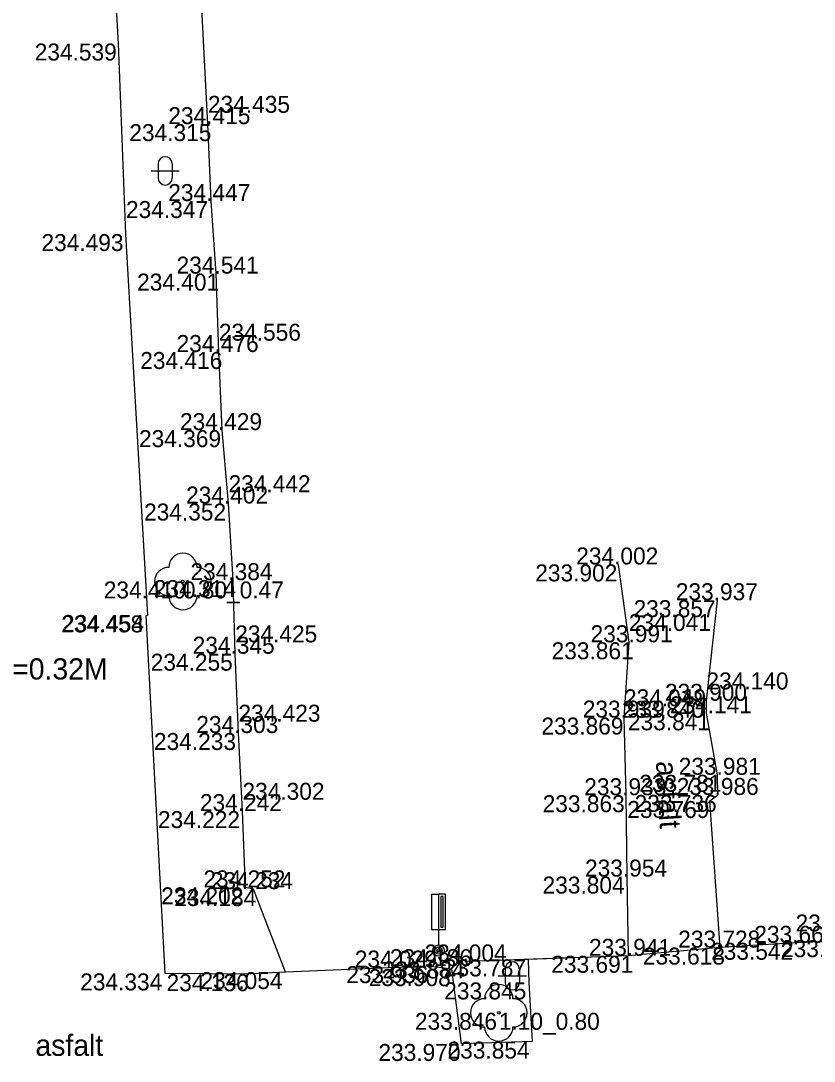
# Model space of a CAD drawing. Extents: x -599516 to -599132, y -1163668 to -1163119.
# Drawn here: x -599502.56 to -599488.54, y -1163175.15 to -1163156.76 of the extents above; entities that cross this region are included whole.
import ezdxf

# ---------------------------------------------------------------- set-up
doc = ezdxf.new("R2010")
doc.units = 0
for name, color, linetype in [('Bod-oznac1', 7, 'Continuous'), ('Bod-oznac2', 7, 'Continuous'), ('Bod-oznac3', 7, 'Continuous'), ('Bod-vyska1', 7, 'Continuous'), ('Bod-vyska2', 7, 'Continuous'), ('Bod-vyska3', 7, 'Continuous'), ('Z_cela-hrobu-dolni-linie', 7, 'Continuous'), ('Z_cela-hrobu-horni-linie', 7, 'Continuous'), ('Z_chodnik', 7, 'Continuous'), ('Z_komunikace', 7, 'Continuous'), ('Z_kultury-znacky', 7, 'Continuous'), ('Z_obvod-kmene-spodek-ve-vysce1_2m', 7, 'Continuous'), ('Z_popis-budov-povrchu', 7, 'Continuous'), ('Z_stromy-kere', 7, 'Continuous'), ('Z_vol-txt-popis-objektu', 7, 'Continuous'), ('Z_znacky-ostatni-orientacni-sloupek', 7, 'Continuous')]:
    doc.layers.add(name, color=color, linetype=linetype)

msp = doc.modelspace()

# ---------------------------------------------------------------- linework, layer by layer
at = {"layer": 'Bod-oznac1'}
for p, q in [((-599500.835, -1163157.161), (-599500.835, -1163157.161)), ((-599499.256, -1163158.586), (-599499.256, -1163158.586)), ((-599499.198, -1163159.946), (-599499.198, -1163159.946)), ((-599500.705, -1163160.53), (-599500.705, -1163160.53)), ((-599499.11, -1163161.229), (-599499.11, -1163161.229)), ((-599499.063, -1163162.615), (-599499.063, -1163162.615)), ((-599499.004, -1163163.996), (-599499.004, -1163163.996)), ((-599498.892, -1163165.294), (-599498.892, -1163165.294)), ((-599492.004, -1163166.371), (-599492.004, -1163166.371)), ((-599499.699, -1163166.672), (-599499.699, -1163166.672)), ((-599498.813, -1163166.648), (-599498.813, -1163166.648)), ((-599490.252, -1163167.003), (-599490.252, -1163167.003)), ((-599500.345, -1163167.272), (-599500.345, -1163167.272)), ((-599500.32, -1163167.265), (-599500.32, -1163167.265)), ((-599491.817, -1163167.747), (-599491.817, -1163167.747)), ((-599498.774, -1163167.949), (-599498.774, -1163167.949)), ((-599490.447, -1163168.781), (-599490.447, -1163168.781)), ((-599491.904, -1163169.078), (-599491.904, -1163169.078)), ((-599490.446, -1163169.003), (-599490.446, -1163169.003)), ((-599498.717, -1163169.351), (-599498.717, -1163169.351)), ((-599490.254, -1163170.09), (-599490.254, -1163170.09)), ((-599491.871, -1163170.451), (-599491.871, -1163170.451)), ((-599490.385, -1163170.553), (-599490.385, -1163170.553)), ((-599490.244, -1163170.446), (-599490.244, -1163170.446)), ((-599498.646, -1163170.732), (-599498.646, -1163170.732)), ((-599491.852, -1163171.889), (-599491.852, -1163171.889)), ((-599498.59, -1163172.08), (-599498.59, -1163172.08)), ((-599498.452, -1163172.111), (-599498.452, -1163172.111)), ((-599490.204, -1163173.145), (-599490.204, -1163173.145)), ((-599488.872, -1163173.06), (-599488.872, -1163173.06)), ((-599495.181, -1163173.198), (-599495.181, -1163173.198)), ((-599493.6, -1163173.353), (-599493.6, -1163173.353)), ((-599491.833, -1163173.29), (-599491.833, -1163173.29)), ((-599495.352, -1163173.473), (-599495.352, -1163173.473)), ((-599494.947, -1163173.526), (-599494.947, -1163173.526)), ((-599494.678, -1163173.39), (-599494.678, -1163173.39)), ((-599500.009, -1163173.601), (-599500.009, -1163173.601)), ((-599498.609, -1163173.615), (-599498.609, -1163173.615)), ((-599497.886, -1163173.578), (-599497.886, -1163173.578)), ((-599493.587, -1163173.761), (-599493.587, -1163173.761)), ((-599494.116, -1163174.298), (-599494.116, -1163174.298)), ((-599494.773, -1163174.849), (-599494.773, -1163174.849)), ((-599493.529, -1163174.807), (-599493.529, -1163174.807))]:
    msp.add_line(p, q, dxfattribs=at)
at = {"layer": 'Bod-oznac2'}
for p, q in [((-599499.256, -1163158.586), (-599499.256, -1163158.586)), ((-599499.198, -1163159.946), (-599499.198, -1163159.946)), ((-599499.11, -1163161.229), (-599499.11, -1163161.229)), ((-599499.063, -1163162.615), (-599499.063, -1163162.615)), ((-599499.004, -1163163.996), (-599499.004, -1163163.996)), ((-599498.892, -1163165.294), (-599498.892, -1163165.294)), ((-599492.004, -1163166.371), (-599492.004, -1163166.371)), ((-599498.813, -1163166.648), (-599498.813, -1163166.648)), ((-599490.252, -1163167.003), (-599490.252, -1163167.003)), ((-599491.817, -1163167.747), (-599491.817, -1163167.747)), ((-599498.774, -1163167.949), (-599498.774, -1163167.949)), ((-599490.447, -1163168.781), (-599490.447, -1163168.781)), ((-599491.904, -1163169.078), (-599491.904, -1163169.078)), ((-599490.446, -1163169.003), (-599490.446, -1163169.003)), ((-599498.717, -1163169.351), (-599498.717, -1163169.351)), ((-599490.254, -1163170.09), (-599490.254, -1163170.09)), ((-599491.871, -1163170.451), (-599491.871, -1163170.451)), ((-599490.244, -1163170.446), (-599490.244, -1163170.446)), ((-599498.646, -1163170.732), (-599498.646, -1163170.732)), ((-599491.852, -1163171.889), (-599491.852, -1163171.889)), ((-599498.59, -1163172.08), (-599498.59, -1163172.08)), ((-599498.452, -1163172.111), (-599498.452, -1163172.111)), ((-599490.204, -1163173.145), (-599490.204, -1163173.145)), ((-599488.872, -1163173.06), (-599488.872, -1163173.06)), ((-599491.833, -1163173.29), (-599491.833, -1163173.29)), ((-599495.352, -1163173.473), (-599495.352, -1163173.473)), ((-599494.678, -1163173.39), (-599494.678, -1163173.39))]:
    msp.add_line(p, q, dxfattribs=at)
at = {"layer": 'Bod-oznac3'}
for p, q in [((-599499.256, -1163158.586), (-599499.256, -1163158.586)), ((-599499.063, -1163162.615), (-599499.063, -1163162.615)), ((-599498.892, -1163165.294), (-599498.892, -1163165.294)), ((-599491.817, -1163167.747), (-599491.817, -1163167.747)), ((-599498.774, -1163167.949), (-599498.774, -1163167.949)), ((-599490.447, -1163168.781), (-599490.447, -1163168.781)), ((-599491.904, -1163169.078), (-599491.904, -1163169.078)), ((-599498.717, -1163169.351), (-599498.717, -1163169.351)), ((-599498.646, -1163170.732), (-599498.646, -1163170.732)), ((-599488.872, -1163173.06), (-599488.872, -1163173.06))]:
    msp.add_line(p, q, dxfattribs=at)
at = {"layer": 'Z_cela-hrobu-dolni-linie'}
msp.add_line((-599493.6, -1163173.353), (-599494.678, -1163173.39), dxfattribs=at)
msp.add_lwpolyline([(-599497.886, -1163173.578), (-599498.452, -1163172.111), (-599498.59, -1163172.08), (-599498.646, -1163170.732), (-599498.717, -1163169.351), (-599498.774, -1163167.949), (-599498.813, -1163166.648), (-599498.892, -1163165.294), (-599499.004, -1163163.996), (-599499.063, -1163162.615), (-599499.11, -1163161.229), (-599499.198, -1163159.946), (-599499.256, -1163158.586), (-599499.406, -1163155.736), (-599499.508, -1163154.372), (-599499.59, -1163152.997), (-599499.718, -1163150.279)], dxfattribs=at)
at = {"layer": 'Z_cela-hrobu-horni-linie'}
for p, q in [((-599490.244, -1163170.446), (-599490.254, -1163170.09)), ((-599490.204, -1163173.145), (-599490.385, -1163170.553)), ((-599495.352, -1163173.473), (-599497.886, -1163173.578))]:
    msp.add_line(p, q, dxfattribs=at)
for points in [[(-599499.198, -1163159.946), (-599499.256, -1163158.586), (-599499.256, -1163158.586), (-599499.406, -1163155.736), (-599499.406, -1163155.736), (-599499.508, -1163154.372), (-599499.508, -1163154.372), (-599499.59, -1163152.997), (-599499.59, -1163152.997), (-599499.718, -1163150.279), (-599496.489, -1163150.097)], [(-599499.004, -1163163.996), (-599499.063, -1163162.615), (-599499.063, -1163162.615), (-599499.11, -1163161.229)], [(-599498.452, -1163172.111), (-599498.59, -1163172.08), (-599498.646, -1163170.732), (-599498.646, -1163170.732), (-599498.717, -1163169.351), (-599498.717, -1163169.351), (-599498.774, -1163167.949), (-599498.774, -1163167.949), (-599498.813, -1163166.648), (-599498.892, -1163165.294), (-599498.892, -1163165.294), (-599499.004, -1163163.996)], [(-599492.004, -1163166.371), (-599491.817, -1163167.747), (-599491.817, -1163167.747), (-599491.904, -1163169.078), (-599491.904, -1163169.078), (-599491.871, -1163170.451)], [(-599490.446, -1163169.003), (-599490.447, -1163168.781), (-599490.447, -1163168.781), (-599490.252, -1163167.003)], [(-599491.852, -1163171.889), (-599491.833, -1163173.29), (-599494.678, -1163173.39)], [(-599487.636, -1163173.014), (-599488.872, -1163173.06), (-599488.872, -1163173.06), (-599490.204, -1163173.145)]]:
    msp.add_lwpolyline(points, dxfattribs=at)
at = {"layer": 'Z_chodnik'}
for points in [[(-599492.004, -1163166.371), (-599491.817, -1163167.747), (-599491.904, -1163169.078), (-599491.871, -1163170.451), (-599491.852, -1163171.889), (-599491.833, -1163173.29)], [(-599490.204, -1163173.145), (-599490.385, -1163170.553), (-599490.244, -1163170.446), (-599490.254, -1163170.09), (-599490.446, -1163169.003), (-599490.447, -1163168.781), (-599490.252, -1163167.003)]]:
    msp.add_lwpolyline(points, dxfattribs=at)
at = {"layer": 'Z_komunikace'}
for points in [[(-599500.835, -1163157.161), (-599501.222, -1163150.305), (-599499.718, -1163150.279)], [(-599500.705, -1163160.53), (-599500.835, -1163157.161)], [(-599494.773, -1163174.849), (-599494.947, -1163173.526), (-599495.352, -1163173.473), (-599497.886, -1163173.578), (-599498.609, -1163173.615), (-599500.009, -1163173.601), (-599500.345, -1163167.272), (-599500.32, -1163167.265), (-599500.705, -1163160.53)], [(-599487.636, -1163173.014), (-599488.872, -1163173.06), (-599490.204, -1163173.145), (-599491.833, -1163173.29), (-599493.6, -1163173.353), (-599493.587, -1163173.761)], [(-599493.587, -1163173.761), (-599493.529, -1163174.807), (-599494.773, -1163174.849)]]:
    msp.add_lwpolyline(points, dxfattribs=at)
at = {"layer": 'Z_kultury-znacky'}
for p, q in [((-599500.137, -1163159.288), (-599500.137, -1163159.538)), ((-599499.887, -1163159.288), (-599499.887, -1163159.538)), ((-599500.262, -1163159.413), (-599499.762, -1163159.413)), ((-599494.003, -1163173.519), (-599494.003, -1163173.769)), ((-599493.753, -1163173.519), (-599493.753, -1163173.769)), ((-599494.128, -1163173.644), (-599493.628, -1163173.644))]:
    msp.add_line(p, q, dxfattribs=at)
for centre, start, end in [((-599500.012, -1163159.288), 0, 180), ((-599500.012, -1163159.538), 180, 0), ((-599493.879, -1163173.519), 0, 180), ((-599493.879, -1163173.769), 180, 0)]:
    msp.add_arc(centre, 0.125, start, end, dxfattribs=at)
at = {"layer": 'Z_stromy-kere'}
for centre in [(-599499.699, -1163166.672), (-599494.116, -1163174.298)]:
    msp.add_circle(centre, 0.025, dxfattribs=at)
for centre, start, end in [((-599499.699, -1163166.422), 0, 180), ((-599499.949, -1163166.672), 90, 270), ((-599499.449, -1163166.672), 270, 90), ((-599499.699, -1163166.922), 180, 0), ((-599494.116, -1163174.048), 0, 180), ((-599494.366, -1163174.298), 90, 270), ((-599493.866, -1163174.298), 270, 90), ((-599494.116, -1163174.548), 180, 0)]:
    msp.add_arc(centre, 0.25, start, end, dxfattribs=at)
at = {"layer": 'Z_znacky-ostatni-orientacni-sloupek'}
for p, q in [((-599495.306, -1163172.198), (-599495.306, -1163172.823)), ((-599495.306, -1163172.198), (-599495.181, -1163172.198)), ((-599495.306, -1163172.823), (-599495.181, -1163172.823)), ((-599495.181, -1163172.823), (-599495.181, -1163173.098))]:
    msp.add_line(p, q, dxfattribs=at)
for points in [[(-599495.181, -1163172.823), (-599495.056, -1163172.823), (-599495.056, -1163172.198), (-599495.181, -1163172.198)], [(-599495.139, -1163172.781), (-599495.098, -1163172.781), (-599495.098, -1163172.241), (-599495.139, -1163172.241)]]:
    msp.add_lwpolyline(points, close=True, dxfattribs=at)
for radius in [0.1, 0.065, 0.03]:
    msp.add_circle((-599495.181, -1163173.198), radius, dxfattribs=at)

# ---------------------------------------------------------------- texts
at = {"layer": 'Bod-vyska1'}
for s, p in [('234.539', (-599502.317, -1163157.461)), ('234.315', (-599500.645, -1163158.886)), ('234.347', (-599500.704, -1163160.246)), ('234.493', (-599502.198, -1163160.83)), ('234.401', (-599500.508, -1163161.529)), ('234.416', (-599500.452, -1163162.915)), ('234.369', (-599500.474, -1163164.296)), ('234.352', (-599500.385, -1163165.594)), ('233.902', (-599493.472, -1163166.671)), ('234.410', (-599501.097, -1163166.972)), ('234.314', (-599500.213, -1163166.948)), ('233.857', (-599491.735, -1163167.303)), ('234.458', (-599501.849, -1163167.572)), ('234.454', (-599501.835, -1163167.565)), ('233.861', (-599493.183, -1163168.047)), ('234.255', (-599500.267, -1163168.249)), ('233.840', (-599491.938, -1163169.081)), ('233.869', (-599493.363, -1163169.378)), ('233.841', (-599491.835, -1163169.303)), ('234.233', (-599500.21, -1163169.651)), ('233.781', (-599491.633, -1163170.39)), ('233.863', (-599493.341, -1163170.751)), ('233.769', (-599491.846, -1163170.853)), ('233.736', (-599491.716, -1163170.746)), ('234.222', (-599500.139, -1163171.032)), ('233.804', (-599493.343, -1163172.189)), ('234.202', (-599500.081, -1163172.38)), ('234.184', (-599499.852, -1163172.411)), ('233.458', (-599489.129, -1163173.314)), ('234.029', (-599496.661, -1163173.498)), ('233.618', (-599491.57, -1163173.445)), ('233.542', (-599490.365, -1163173.36)), ('233.787', (-599495.085, -1163173.653)), ('233.691', (-599493.188, -1163173.59)), ('233.936', (-599496.811, -1163173.773)), ('233.908', (-599496.415, -1163173.826)), ('233.884', (-599496.171, -1163173.69)), ('234.334', (-599501.513, -1163173.901)), ('234.136', (-599499.987, -1163173.915)), ('234.054', (-599499.388, -1163173.878)), ('233.845', (-599495.08, -1163174.061)), ('233.846', (-599495.598, -1163174.598)), ('233.970', (-599496.243, -1163175.149)), ('233.854', (-599495.022, -1163175.107))]:
    msp.add_text(s, height=0.3, dxfattribs=at).set_placement(p)
at = {"layer": 'Bod-vyska2'}
for s, p in [('234.415', (-599499.956, -1163158.586)), ('234.447', (-599499.957, -1163159.946)), ('234.541', (-599499.81, -1163161.229)), ('234.476', (-599499.81, -1163162.615)), ('234.429', (-599499.75, -1163163.996)), ('234.402', (-599499.643, -1163165.294)), ('234.002', (-599492.748, -1163166.371)), ('234.384', (-599499.565, -1163166.648)), ('233.937', (-599490.988, -1163167.003)), ('233.991', (-599492.494, -1163167.747)), ('234.345', (-599499.526, -1163167.949)), ('233.900', (-599491.18, -1163168.781)), ('233.939', (-599492.633, -1163169.078)), ('234.141', (-599491.094, -1163169.003)), ('234.303', (-599499.462, -1163169.351)), ('233.981', (-599490.937, -1163170.09)), ('233.933', (-599492.606, -1163170.451)), ('233.986', (-599490.973, -1163170.446)), ('234.242', (-599499.398, -1163170.732)), ('233.954', (-599492.593, -1163171.889)), ('234.252', (-599499.336, -1163172.08)), ('234.234', (-599499.204, -1163172.111)), ('233.662', (-599489.601, -1163173.06)), ('233.941', (-599492.522, -1163173.29)), ('233.728', (-599490.946, -1163173.145)), ('234.186', (-599496.041, -1163173.473)), ('234.004', (-599495.428, -1163173.39))]:
    msp.add_text(s, height=0.3, dxfattribs=at).set_placement(p)
at = {"layer": 'Bod-vyska3'}
for s, p in [('234.435', (-599499.256, -1163158.386)), ('234.556', (-599499.063, -1163162.415)), ('234.442', (-599498.892, -1163165.094)), ('234.041', (-599491.817, -1163167.547)), ('234.425', (-599498.774, -1163167.749)), ('234.140', (-599490.447, -1163168.581)), ('234.049', (-599491.904, -1163168.878)), ('234.423', (-599498.717, -1163169.151)), ('234.302', (-599498.646, -1163170.532)), ('233.702', (-599488.872, -1163172.86))]:
    msp.add_text(s, height=0.3, dxfattribs=at).set_placement(p)
at = {"layer": 'Z_obvod-kmene-spodek-ve-vysce1_2m'}
for s, p in [('0.80_0.47', (-599499.699, -1163166.972)), ('1.10_0.80', (-599494.116, -1163174.598))]:
    msp.add_text(s, height=0.3, dxfattribs=at).set_placement(p)
at = {"layer": 'Z_popis-budov-povrchu'}
msp.add_text('asfalt', height=0.375, rotation=273.4503, dxfattribs=at).set_placement((-599491.34, -1163169.854))
msp.add_text('asfalt', height=0.375, dxfattribs=at).set_placement((-599502.304, -1163175.059))
at = {"layer": 'Z_vol-txt-popis-objektu'}
msp.add_text('KRYTKA-D=0.32M', height=0.375, dxfattribs=at).set_placement((-599505.251, -1163168.405))

doc.saveas('drawing.dxf')
